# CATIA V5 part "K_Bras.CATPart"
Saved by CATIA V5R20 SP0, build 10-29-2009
Part number: Bras
Bounding box of the stored display mesh (mm): x -21 to 21, y 8.963 to 190.068, z 128.325 to 189.747
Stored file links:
  G:\Khaled_CFAO_2011\ST2M\ST2M_GR1\hgrenier\Khaled\CAD_ThinkMOTION\K_Bras.CATPart
  C:\Users\Tom\Documents\Cours 2A\CFAO\Projet thinkmotion\Hugo\porte_outil.CATProduct
  G:\Khaled_CFAO_2011\ST2M\ST2M_GR1\hgrenier\Khaled\CAD_ThinkMOTION\K_Squelette.CATPart
  G:\Khaled_CFAO_2011\ST2M\ST2M_GR1\hgrenier\Khaled\CAD_ThinkMOTION\K_CorpsVerin1.CATPart
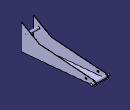
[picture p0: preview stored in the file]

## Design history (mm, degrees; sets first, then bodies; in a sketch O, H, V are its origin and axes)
Parameters
  diametre_trou_bielle2 = 4.78 mm
  diametre_trou_bras_godet = 6 mm
External parameters (linked from other documents)
  External.diametre_trou_bras_verin1 = 6 mm
Set1
  Plane1 "Plan_bielle2": linked copy from another document
  Point1 "Centre_bras/godet": linked copy from another document
  Plane2 "plan_sym": linked copy from another document
  Point2 "Centre_bras/bielle2": linked copy from another document
  Point3 "Centre_bras_verin1": linked copy from another document
  Plane3: linked copy from another document
  Plane4 "Plan_godet": linked copy from another document
Body1 (main body)
  Sketch1 on Plane1, origin (15, 0, 0), H (0, 1, 0), V (0, 0, 1)
    arc A1 centre (184.534, 150.027) radius 5.5364 from (184.6547, 144.4919) to (184.9484, 155.5479) ccw
    point P1 (184.534, 150.027)
    reference projected point E1 (184.534, 150.027) from Point1
    line L1 (8.9626, 128.3253) -> (184.6547, 144.4919)
    line L2 (51.9483, 165.532) -> (184.9484, 155.5479)
    line L3 (8.9626, 128.3253) -> (8.9626, 189.7468)
    line L4 (51.9483, 165.532) -> (8.9626, 189.7468)
    coincidence: P1 E1
    tangency: L2 A1
    vertical: L3 V
  Pad1: profile Sketch1, direction (-1, 0, 0), up to Plane3
  Shell1: IntOffset 1, Face (face of Pad1 from Sketch1.L2; face of Pad1 from Sketch1.L4; face of Pad1 from Sketch1.L3), ExtOffset 0, ShellSkin (InitFace face of Pad1 from Sketch1.L1, IntOffset 1, ExtOffset 0; InitFace start face of Pad1, IntOffset 1, ExtOffset 0; InitFace end face of Pad1, IntOffset 1, ExtOffset 0)
  Sketch2 on face of Shell1, origin (-14, 0, 0), H (0, 1, 0), V (0, 0, 1)
    circle A1 centre (184.534, 150.027) radius 3.3363
    point P1 (184.534, 150.027)
    reference projected point E1 (184.534, 150.027) from Point1
    coincidence: P1 E1
  Pad2: profile Sketch2, direction (1, 0, 0), up to the existing solid (limit type 2)
  Sketch3 on start face of Pad1, origin (15, 0, 0), H (0, 1, 0), V (0, 0, 1)
    circle A1 centre (165.417, 150.684) radius 2.39
    point P1 (165.417, 150.684)
    reference projected point E1 (165.417, 150.684) from Point2
    radius A1 = 2.39 {= diametre_trou_bielle2 /2}
    coincidence: P1 E1
  Pocket1: profile Sketch3, direction (-1, 0, 0), length 60
  Sketch4 on face of Shell1, origin (14, 0, 0), H (0, -1, 0), V (0, 0, 1)
    circle A1 centre (-21.719, 169.887) radius 3
    point P1 (-21.719, 169.887)
    reference projected point E1 (-21.719, 169.887) from Point3
    radius A1 = 3 {= External.diametre_trou_bras_verin1 /2}
    coincidence: P1 E1
  Pad3: profile Sketch4, direction (-1, 0, 0), up to the existing solid (limit type 2)
  Sketch5 on start face of Pad1, origin (15, 0, 0), H (0, 1, 0), V (0, 0, 1)
    circle A1 centre (184.534, 150.027) radius 3
    point P1 (184.534, 150.027)
    reference projected point E1 (184.534, 150.027) from Point1
    radius A1 = 3 {= diametre_trou_bras_godet /2}
    coincidence: P1 E1
  Pad4: profile Sketch5, direction (1, 0, 0), up to Plane4
  Sketch6 on end face of Pad1, origin (-15, 0, 0), H (0, -1, 0), V (0, 0, 1)
    circle A1 centre (-184.534, 150.027) radius 3
    point P1 (-184.534, 150.027)
    reference projected point E1 (-184.534, 150.027) from Point1
    radius A1 = 3 {= diametre_trou_bras_godet /2}
    coincidence: P1 E1
  Pad5: profile Sketch6, direction (-1, 0, 0), length 6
